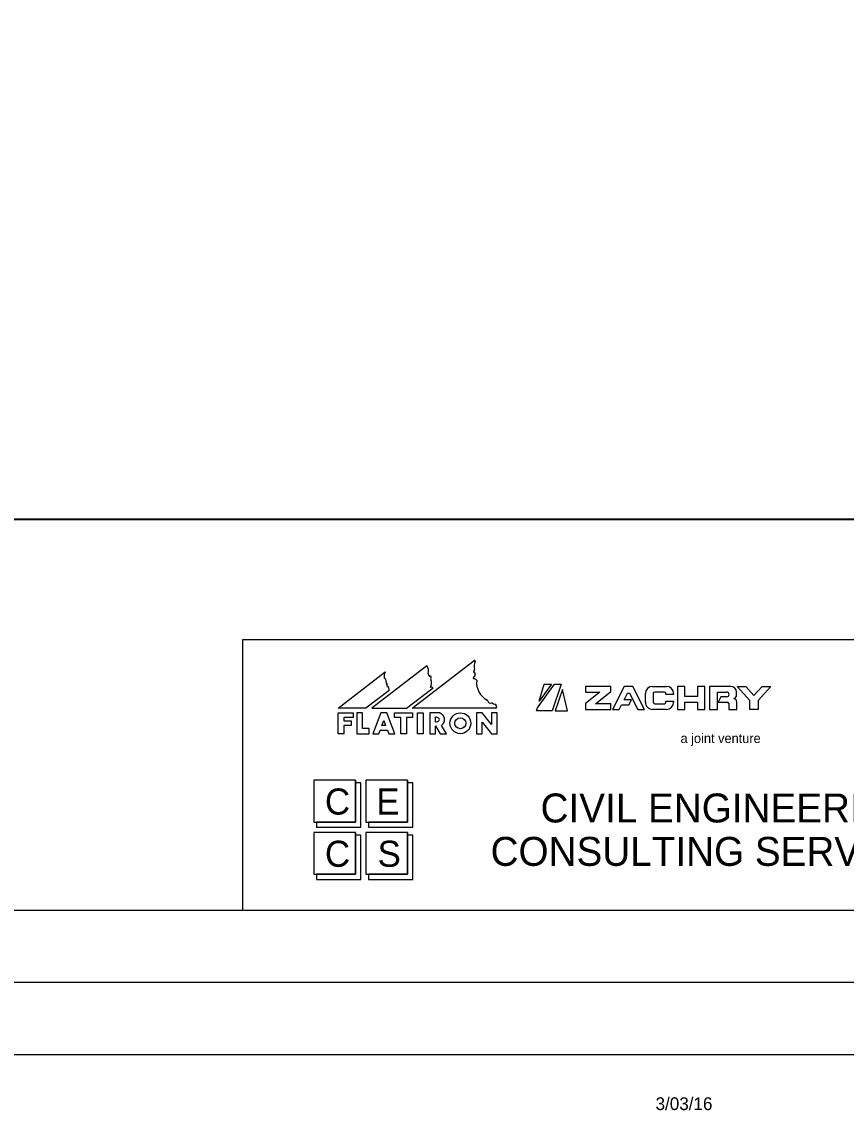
# Model space of a CAD drawing. Extents: x -2251 to 10196, y -13470 to 1199.
# Drawn here: x 3737.3 to 4022.4, y -5969.8 to -5593.7 of the extents above; entities that cross this region are included whole.
import ezdxf

# ---------------------------------------------------------------- set-up
doc = ezdxf.new("R2010")
doc.units = 0
for name, color, linetype in [('Level 3', 7, 'Continuous'), ('RD_SHT_Bndy', 7, 'Continuous'), ('RD_SHT_Iplotshp', 7, 'Continuous'), ('RD_SHT_Logo', 7, 'Continuous'), ('RD_SHT_Misc1', 7, 'Continuous'), ('RD_SHT_Snap', 7, 'Continuous'), ('RD_SHT_TX', 7, 'Continuous'), ('RD_TX_RoadID', 7, 'Continuous')]:
    doc.layers.add(name, color=color, linetype=linetype)

msp = doc.modelspace()

# ---------------------------------------------------------------- linework, layer by layer
at = {"layer": 'Level 3'}
msp.add_line((3965.07, -5863.99), (3965.07, -5863.99), dxfattribs=at)
msp.add_line((3965.07, -5863.99), (3965.07, -5863.99), dxfattribs=at)
msp.add_line((3965.07, -5863.99), (3965.07, -5863.99), dxfattribs=at)
msp.add_line((3965.07, -5863.99), (3965.07, -5863.99), dxfattribs=at)
at = {"layer": 'RD_SHT_Bndy'}
for p, q in [((2603.1, -5900.65), (4278.1, -5900.65)), ((4291.65, -5925.65), (2531.65, -5925.65)), ((4291.6, -5950.7), (2531.6, -5950.65))]:
    msp.add_line(p, q, dxfattribs=at)
msp.add_lwpolyline([(2653.4, -4901.26), (4231.08, -4901.26), (4231.08, -5765.57), (2653.4, -5765.57)], close=True, dxfattribs=at)
at = {"layer": 'RD_SHT_Iplotshp'}
msp.add_lwpolyline([(2496.65, -4825.65), (4296.65, -4825.65), (4296.65, -5925.65), (2496.65, -5925.65)], close=True, dxfattribs=at)
at = {"layer": 'RD_SHT_Logo'}
for p, q in [((3872.32, -5830.86), (3893.74, -5814.44)), ((3846.7, -5830.86), (3862.98, -5818.38)), ((3877.35, -5816.27), (3858.31, -5830.86)), ((3915.56, -5830.77), (3921.47, -5822.59)), ((3920.48, -5822.59), (3916.24, -5828.47)), ((3916.24, -5828.47), (3917.96, -5822.59)), ((3917.96, -5822.59), (3920.48, -5822.59)), ((3923.82, -5822.59), (3920.68, -5831.76)), ((3921.47, -5822.59), (3923.82, -5822.59)), ((3864.27, -5824.74), (3856.29, -5830.86)), ((3870.3, -5830.86), (3879.48, -5823.82)), ((3924.24, -5824.44), (3921.74, -5831.76)), ((3925.99, -5831.76), (3924.24, -5824.44)), ((3940.93, -5823.35), (3932.22, -5823.35)), ((3932.22, -5823.35), (3932.22, -5825.3)), ((3937.2, -5825.3), (3932.22, -5829.24)), ((3932.22, -5825.3), (3937.2, -5825.3)), ((3935.63, -5829.35), (3940.93, -5825.16)), ((3940.93, -5825.16), (3940.93, -5823.35)), ((3945.58, -5823.35), (3941.53, -5831.3)), ((3945.57, -5827.99), (3946.71, -5825.75)), ((3948.58, -5823.35), (3945.58, -5823.35)), ((3946.71, -5825.75), (3947.44, -5825.75)), ((3947.44, -5825.75), (3950.27, -5831.3)), ((3952.63, -5831.3), (3948.58, -5823.35)), ((3952.94, -5828.8), (3952.94, -5825.85)), ((3955.44, -5823.35), (3960.18, -5823.35)), ((3955.64, -5825.8), (3955.64, -5828.85)), ((3959.48, -5825.3), (3956.14, -5825.3)), ((3959.98, -5826.15), (3959.98, -5825.8)), ((3962.68, -5826.15), (3959.98, -5826.15)), ((3962.68, -5825.85), (3962.68, -5826.15)), ((3966.62, -5823.35), (3964.02, -5823.35)), ((3964.02, -5823.35), (3964.02, -5831.3)), ((3966.62, -5826.8), (3966.62, -5823.35)), ((3970.9, -5826.8), (3966.62, -5826.8)), ((3970.9, -5823.35), (3970.9, -5826.8)), ((3973.51, -5823.35), (3970.9, -5823.35)), ((3973.5, -5831.3), (3973.51, -5823.35)), ((3982.43, -5823.35), (3975.13, -5823.35)), ((3975.13, -5823.35), (3975.13, -5831.3)), ((3977.83, -5831.3), (3977.83, -5825.31)), ((3977.83, -5825.31), (3981.07, -5825.31)), ((3979.03, -5826.97), (3978.11, -5828.77)), ((3981.07, -5826.97), (3979.03, -5826.97)), ((3984.43, -5826.36), (3984.43, -5825.35)), ((3984.68, -5823.35), (3987.64, -5823.35)), ((3989.08, -5828.24), (3984.68, -5823.35)), ((3987.64, -5823.35), (3990.48, -5826.51)), ((3990.48, -5826.51), (3993.32, -5823.35)), ((3996.28, -5823.35), (3991.88, -5828.24)), ((3993.32, -5823.35), (3996.28, -5823.35)), ((3932.22, -5829.24), (3932.22, -5831.3)), ((3940.93, -5829.35), (3935.63, -5829.35)), ((3940.93, -5831.3), (3940.93, -5829.35)), ((3943.88, -5831.3), (3944.65, -5829.79)), ((3944.65, -5829.79), (3947.23, -5829.79)), ((3948.15, -5827.99), (3945.57, -5827.99)), ((3947.23, -5829.79), (3948.15, -5827.99)), ((3956.14, -5829.35), (3959.48, -5829.35)), ((3959.98, -5828.5), (3962.68, -5828.5)), ((3959.98, -5828.85), (3959.98, -5828.5)), ((3962.68, -5828.5), (3962.68, -5828.8)), ((3966.62, -5831.3), (3966.62, -5828.8)), ((3966.62, -5828.8), (3970.9, -5828.8)), ((3970.9, -5828.8), (3970.9, -5831.3)), ((3978.11, -5828.77), (3981.24, -5828.77)), ((3981.74, -5829.27), (3981.74, -5831.3)), ((3983.68, -5827.6), (3983.68, -5827.47)), ((3984.54, -5831.3), (3984.54, -5828.76)), ((3989.08, -5831.3), (3989.08, -5828.24)), ((3991.88, -5828.24), (3991.88, -5831.3)), ((3856.29, -5830.86), (3846.7, -5830.86)), ((3846.72, -5839.7), (3846.72, -5832.5)), ((3846.72, -5832.5), (3851.82, -5832.5)), ((3851.82, -5834.15), (3848.67, -5834.15)), ((3848.67, -5834.15), (3848.67, -5835.21)), ((3851.82, -5832.5), (3851.82, -5834.15)), ((3855.12, -5832.5), (3853.17, -5832.5)), ((3853.17, -5832.5), (3853.17, -5839.7)), ((3855.12, -5837.9), (3855.12, -5832.5)), ((3858.31, -5830.86), (3870.3, -5830.86)), ((3861.42, -5832.5), (3858.65, -5839.71)), ((3863.52, -5832.5), (3861.42, -5832.5)), ((3866.28, -5839.71), (3863.52, -5832.5)), ((3866.22, -5834.15), (3866.22, -5832.5)), ((3866.22, -5832.5), (3872.37, -5832.5)), ((3868.32, -5834.15), (3866.22, -5834.15)), ((3868.32, -5839.71), (3868.32, -5834.15)), ((3872.37, -5834.15), (3870.27, -5834.15)), ((3870.27, -5834.15), (3870.27, -5839.71)), ((3901.19, -5830.86), (3872.32, -5830.86)), ((3872.37, -5832.5), (3872.37, -5834.15)), ((3874.17, -5839.71), (3874.17, -5832.5)), ((3874.17, -5832.5), (3876.12, -5832.5)), ((3876.12, -5832.5), (3876.12, -5839.71)), ((3881.8, -5832.5), (3878.38, -5832.5)), ((3878.38, -5832.5), (3878.38, -5839.71)), ((3880.33, -5835.66), (3880.33, -5834.01)), ((3896.52, -5832.5), (3894.57, -5832.5)), ((3894.57, -5832.5), (3894.57, -5839.71)), ((3899.67, -5836.53), (3896.52, -5832.5)), ((3901.62, -5832.5), (3899.67, -5832.5)), ((3899.67, -5832.5), (3899.67, -5836.53)), ((3901.62, -5839.71), (3901.62, -5832.5)), ((3915.27, -5831.76), (3915.56, -5830.77)), ((3920.68, -5831.76), (3915.27, -5831.76)), ((3921.74, -5831.76), (3925.99, -5831.76)), ((3932.22, -5831.3), (3940.93, -5831.3)), ((3941.53, -5831.3), (3943.88, -5831.3)), ((3950.27, -5831.3), (3952.63, -5831.3)), ((3960.18, -5831.3), (3955.44, -5831.3)), ((3964.02, -5831.3), (3966.62, -5831.3)), ((3970.9, -5831.3), (3973.5, -5831.3)), ((3975.13, -5831.3), (3977.83, -5831.3)), ((3981.74, -5831.3), (3984.54, -5831.3)), ((3991.88, -5831.3), (3989.08, -5831.3)), ((3848.67, -5835.21), (3851.22, -5835.21)), ((3851.22, -5836.86), (3848.67, -5836.86)), ((3848.67, -5836.86), (3848.67, -5839.7)), ((3851.22, -5835.21), (3851.22, -5836.86)), ((3857.37, -5837.9), (3855.12, -5837.9)), ((3857.37, -5839.71), (3857.37, -5837.9)), ((3861.83, -5836.86), (3862.47, -5835.2)), ((3863.1, -5836.86), (3861.83, -5836.86)), ((3862.47, -5835.2), (3863.1, -5836.86)), ((3880.33, -5839.71), (3880.33, -5837.02)), ((3880.33, -5837.02), (3881.94, -5839.71)), ((3884.16, -5839.71), (3882.43, -5836.82)), ((3896.52, -5839.71), (3896.52, -5835.67)), ((3896.52, -5835.67), (3899.67, -5839.71)), ((3848.67, -5839.7), (3846.72, -5839.7)), ((3853.17, -5839.7), (3857.37, -5839.71)), ((3858.65, -5839.71), (3860.74, -5839.71)), ((3860.74, -5839.71), (3861.2, -5838.51)), ((3861.2, -5838.51), (3863.74, -5838.51)), ((3863.74, -5838.51), (3864.2, -5839.71)), ((3864.2, -5839.71), (3866.28, -5839.71)), ((3870.27, -5839.71), (3868.32, -5839.71)), ((3876.12, -5839.71), (3874.17, -5839.71)), ((3878.38, -5839.71), (3880.33, -5839.71)), ((3881.94, -5839.71), (3884.16, -5839.71)), ((3894.57, -5839.71), (3896.52, -5839.71)), ((3899.67, -5839.71), (3901.62, -5839.71)), ((3852.67, -5855.79), (3838.28, -5855.79)), ((3838.28, -5855.79), (3838.28, -5870.23)), ((3852.67, -5870.23), (3852.67, -5855.79)), ((3852.67, -5855.79), (3852.67, -5870.23)), ((3854.48, -5856.7), (3852.67, -5856.7)), ((3854.48, -5872.03), (3854.48, -5856.7)), ((3870.67, -5855.79), (3856.27, -5855.79)), ((3856.27, -5855.79), (3856.27, -5870.23)), ((3870.67, -5870.23), (3870.67, -5855.79)), ((3870.67, -5855.79), (3870.67, -5870.23)), ((3872.48, -5856.7), (3870.67, -5856.7)), ((3872.48, -5872.03), (3872.48, -5856.7)), ((3838.28, -5870.23), (3852.67, -5870.23)), ((3852.67, -5870.23), (3839.17, -5870.23)), ((3839.17, -5870.23), (3839.17, -5872.03)), ((3839.17, -5872.03), (3854.48, -5872.03)), ((3856.27, -5870.23), (3870.67, -5870.23)), ((3870.67, -5870.23), (3857.18, -5870.23)), ((3857.18, -5870.23), (3857.18, -5872.03)), ((3857.18, -5872.03), (3872.48, -5872.03)), ((3852.67, -5873.84), (3838.28, -5873.84)), ((3838.28, -5873.84), (3838.28, -5888.27)), ((3852.67, -5888.27), (3852.67, -5873.84)), ((3852.67, -5873.84), (3852.67, -5888.27)), ((3854.48, -5874.74), (3852.67, -5874.74)), ((3854.48, -5890.07), (3854.48, -5874.74)), ((3870.67, -5873.84), (3856.27, -5873.84)), ((3856.27, -5873.84), (3856.27, -5888.27)), ((3870.67, -5888.27), (3870.67, -5873.84)), ((3870.67, -5873.84), (3870.67, -5888.27)), ((3872.48, -5874.74), (3870.67, -5874.74)), ((3872.48, -5890.07), (3872.48, -5874.74)), ((3838.28, -5888.27), (3852.67, -5888.27)), ((3852.67, -5888.27), (3839.17, -5888.27)), ((3839.17, -5888.27), (3839.17, -5890.07)), ((3839.17, -5890.07), (3854.48, -5890.07)), ((3856.27, -5888.27), (3870.67, -5888.27)), ((3870.67, -5888.27), (3857.18, -5888.27)), ((3857.18, -5888.27), (3857.18, -5890.07)), ((3857.18, -5890.07), (3872.48, -5890.07))]:
    msp.add_line(p, q, dxfattribs=at)
for radius in [3.6, 1.9]:
    msp.add_circle((3888.95, -5836.1), radius, dxfattribs=at)
for centre, radius, start, end in [((3897.87, -5816.34), 4.17, 156.4699, 195.3053), ((3893.86, -5814.6), 0.2, 336.4699, 127.4657), ((3866.29, -5820.12), 3.74, 152.2252, 185.8662), ((3875.05, -5818.02), 2.89, 342.0343, 37.2653), ((3877.99, -5818.97), 0.2, 162.0343, 220.8638), ((3876.86, -5819.95), 1.3, 11.8745, 40.8638), ((3891.59, -5818.37), 2.7, 313.0036, 343.6807), ((3893.73, -5818.39), 0.2, 129.4079, 246.863), ((3893.13, -5817.66), 0.749, 309.4079, 17.0499), ((3893.27, -5819.47), 0.973, 20.4113, 66.863), ((3862.1, -5821.62), 1.21, 351.6466, 67.1294), ((3864.29, -5821.94), 1, 171.6466, 221.9371), ((3863.11, -5823.01), 0.592, 327.6019, 41.9371), ((3878.32, -5819.64), 0.2, 191.8745, 279.8173), ((3878.44, -5820.33), 0.499, 44.4799, 99.8173), ((3875.8, -5822.18), 3.16, 331.2486, 18.4584), ((3879.5, -5820.72), 0.843, 144.641, 212.5499), ((3878.65, -5820.12), 0.2, 324.641, 44.4799), ((3893.57, -5820.5), 0.2, 133.0036, 262.3069), ((3893.31, -5822.44), 1.76, 45.283, 82.3069), ((3894.4, -5821.33), 0.2, 353.8329, 45.283), ((3901.36, -5822.08), 6.8, 173.8329, 242.3928), ((3863.3, -5824.33), 1.05, 337.4201, 73.1261), ((3878.92, -5824.44), 0.827, 48.0701, 115.7229), ((3955.44, -5825.85), 2.5, 89.9984, 179.9984), ((3956.14, -5825.8), 0.5, 89.9984, 179.9984), ((3959.48, -5825.8), 0.5, 359.9984, 89.9984), ((3960.18, -5825.85), 2.5, 359.9984, 89.9984), ((3981.07, -5826.14), 0.831, 269.9984, 89.9984), ((3982.43, -5825.35), 2, 359.9984, 89.9984), ((3983.23, -5826.36), 1.2, 291.95, 359.9984), ((3898.12, -5828.28), 0.2, 9.0833, 62.3928), ((3899.35, -5828.09), 1.04, 189.0833, 295.769), ((3899.89, -5829.21), 0.2, 33.7112, 115.769), ((3900.89, -5828.54), 1.01, 213.7112, 268.6299), ((3900.86, -5829.74), 0.2, 78.9712, 88.6299), ((3900.75, -5830.3), 0.767, 320.912, 78.9712), ((3955.44, -5828.8), 2.5, 179.9984, 269.9984), ((3956.14, -5828.85), 0.5, 179.9984, 269.9984), ((3959.48, -5828.85), 0.5, 269.9984, 359.9984), ((3960.18, -5828.8), 2.5, 269.9984, 359.9984), ((3981.24, -5829.27), 0.5, 359.9984, 89.9984), ((3983.34, -5828.76), 1.2, 359.9984, 73.7977), ((3901.19, -5830.66), 0.2, 269.9984, 320.912)]:
    msp.add_arc(centre, radius, start, end, dxfattribs=at)
msp.add_ellipse((3880.33, -5834.83), major_axis=(1.36, 0), ratio=0.609965, start_param=4.712389, end_param=7.853982, dxfattribs=at)
msp.add_open_spline([(3882.43, -5836.82), (3882.51, -5836.76), (3882.59, -5836.7), (3882.81, -5836.49), (3882.95, -5836.34), (3883.13, -5836.07), (3883.19, -5835.97), (3883.29, -5835.77), (3883.34, -5835.66), (3883.41, -5835.44), (3883.44, -5835.32), (3883.47, -5835.08), (3883.48, -5834.96), (3883.48, -5834.71), (3883.47, -5834.59), (3883.44, -5834.35), (3883.41, -5834.23), (3883.34, -5834.01), (3883.29, -5833.9), (3883.19, -5833.7), (3883.13, -5833.6), (3882.95, -5833.33), (3882.81, -5833.18), (3882.52, -5832.91), (3882.37, -5832.8), (3882.08, -5832.63), (3881.94, -5832.56), (3881.8, -5832.5)], degree=3, dxfattribs=at)
at = {"layer": 'RD_SHT_Misc1'}
msp.add_lwpolyline([(4296.65, -5925.65), (4296.68, -4825.65), (2596.68, -4825.6), (2596.65, -5925.6)], close=True, dxfattribs=at)
at = {"layer": 'RD_SHT_Snap'}
msp.add_lwpolyline([(2508.15, -4825.65), (4308.15, -4825.65), (4308.15, -5925.65), (2508.15, -5925.65)], close=True, dxfattribs=at)
at = {"layer": 'RD_SHT_TX'}
for p, q in [((3813.76, -5900.65), (3813.76, -5807.15)), ((3813.76, -5900.65), (3813.76, -5807.15)), ((3813.76, -5807.15), (4278.1, -5807.15))]:
    msp.add_line(p, q, dxfattribs=at)
at = {"layer": 'RD_TX_RoadID'}
msp.add_lwpolyline([(2650.54, -5765.73), (4233.93, -5765.73), (4233.93, -4962.61), (2650.54, -4962.61)], close=True, dxfattribs=at)

# ---------------------------------------------------------------- texts
at = {"layer": 'RD_SHT_Logo'}
msp.add_text('a joint venture', height=3.3, rotation=359.9984, dxfattribs=at).set_placement((3965.08, -5842.93))
for s, height, p in [('C', 9.02, (3842.11, -5867.66)), ('E', 9.02, (3859.9, -5867.66)), ('CIVIL ENGINEERING', 10, (3916.67, -5870.38)), ('CONSULTING SERVICES, INC.', 10, (3899.39, -5885.38)), ('C', 9.02, (3842.11, -5885.71)), ('S', 9.02, (3860.32, -5885.71))]:
    msp.add_text(s, height=height, dxfattribs=at).set_placement(p)
at = {"layer": 'RD_SHT_TX'}
msp.add_text('3/03/16', height=4.408, dxfattribs=at).set_placement((3956.45, -5969.78))

doc.saveas('drawing.dxf')
